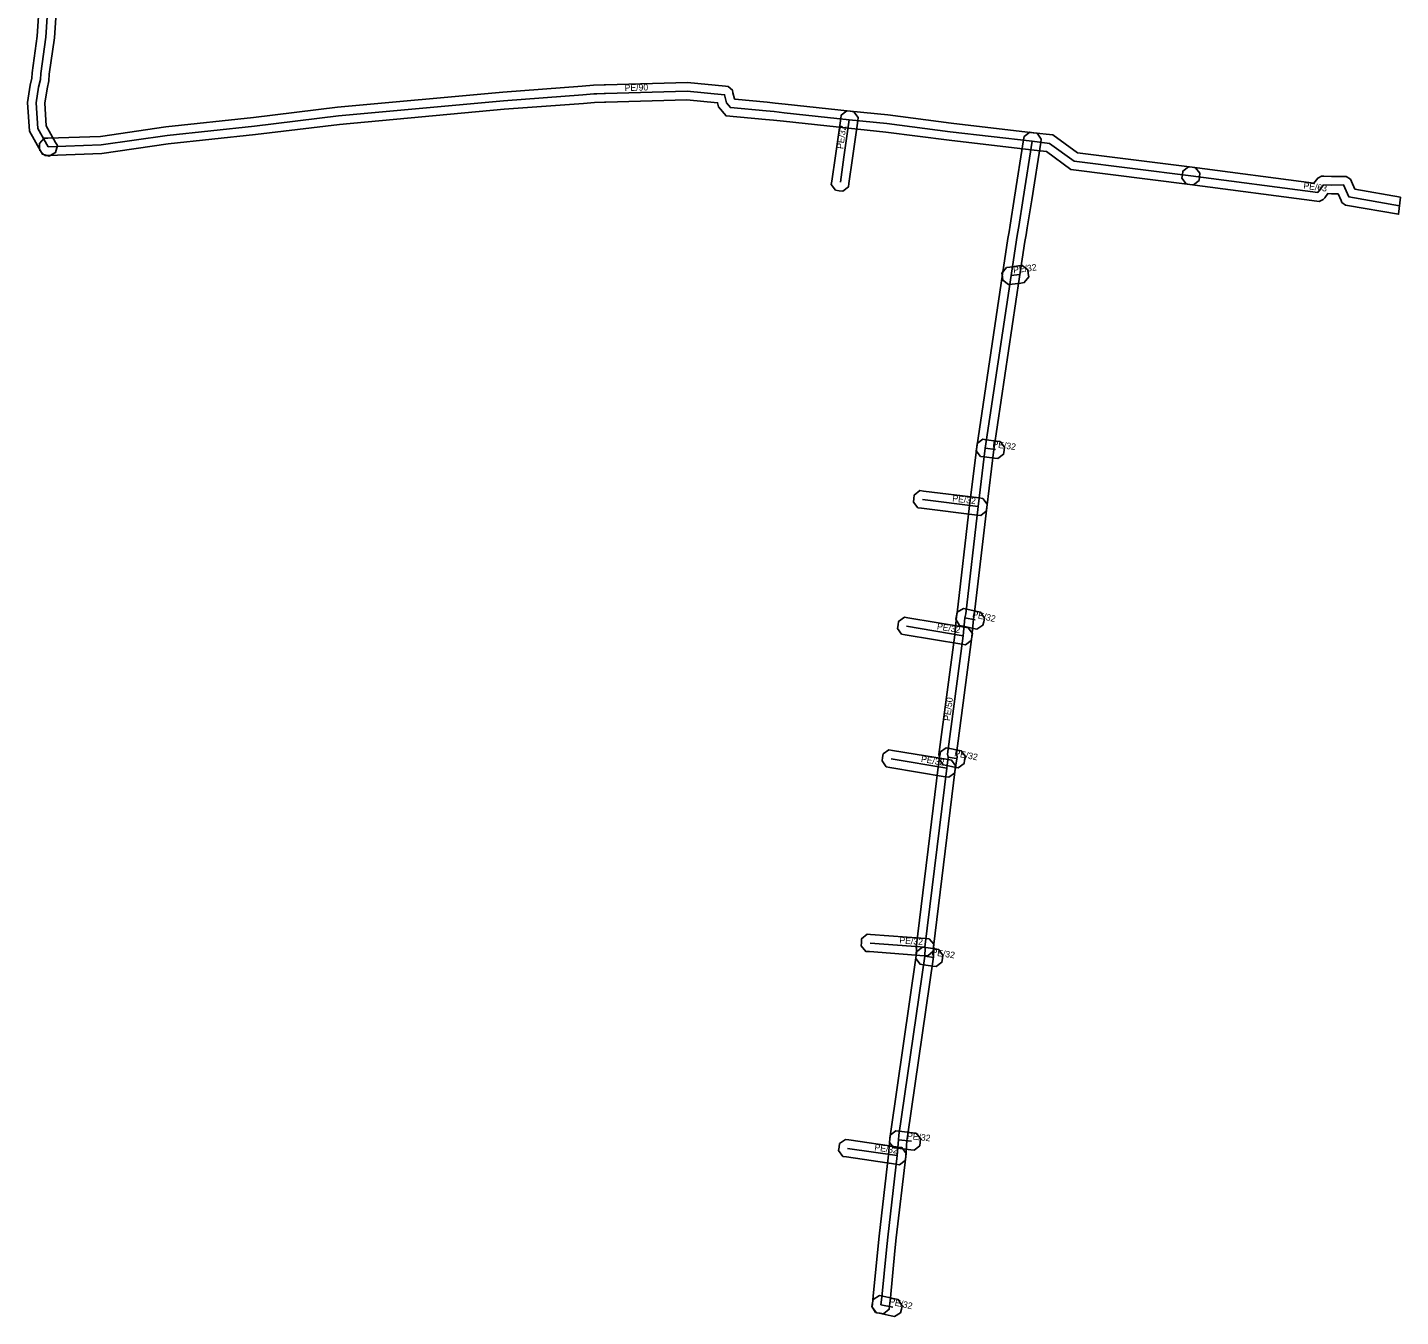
# Model space of a CAD drawing. Extents: x -772893 to -772575, y -1033735 to -1033288.
# Drawn here: x -772764.2 to -772605.1, y -1033735.2 to -1033585.9 of the extents above; entities that cross this region are included whole.
import ezdxf

# ---------------------------------------------------------------- set-up
doc = ezdxf.new("R2010")
doc.units = 0
for name, color, linetype in [('1', 7, 'Continuous'), ('24', 7, 'Continuous'), ('30', 7, 'Continuous')]:
    doc.layers.add(name, color=color, linetype=linetype)

msp = doc.modelspace()

# ---------------------------------------------------------------- linework, layer by layer
at = {"layer": '1'}
msp.add_lwpolyline([(-772760.91, -1033584.82), (-772761.08, -1033587.14), (-772761.67, -1033591.34), (-772761.7, -1033592.11), (-772761.93, -1033593.03), (-772762.18, -1033594.7), (-772762.01, -1033597.34), (-772760.93, -1033599.25), (-772760.72, -1033599.61), (-772760.95, -1033600.41), (-772761.31, -1033600.61), (-772761.67, -1033600.82), (-772762.46, -1033600.59), (-772762.67, -1033600.23), (-772763.97, -1033597.93), (-772764.19, -1033594.61), (-772763.89, -1033592.62), (-772763.69, -1033591.82), (-772763.66, -1033591.17), (-772763.07, -1033586.93), (-772762.91, -1033584.62)], dxfattribs=at)
for points in [[(-772629.13, -1033604.15), (-772629.54, -1033604.1), (-772643.31, -1033602.36), (-772646.16, -1033600.31), (-772647.92, -1033600.1), (-772657.42, -1033599), (-772664.77, -1033598.04), (-772669.1, -1033597.61), (-772676.63, -1033596.79), (-772677.79, -1033596.67), (-772678.7, -1033596.59), (-772683.27, -1033596.17), (-772684.14, -1033595.12), (-772684.25, -1033594.65), (-772687.8, -1033594.3), (-772697.19, -1033594.58), (-772697.34, -1033594.58), (-772698.52, -1033594.63), (-772699.79, -1033594.72), (-772708.97, -1033595.41), (-772728.04, -1033597.15), (-772737.78, -1033598.34), (-772747.9, -1033599.42), (-772755.58, -1033600.54), (-772761.76, -1033600.74), (-772762.18, -1033600.76), (-772762.78, -1033600.19), (-772762.8, -1033599.78), (-772762.81, -1033599.36), (-772762.24, -1033598.76), (-772761.83, -1033598.74), (-772755.75, -1033598.54), (-772748.15, -1033597.44), (-772738.01, -1033596.36), (-772728.26, -1033595.17), (-772709.14, -1033593.41), (-772699.94, -1033592.73), (-772698.64, -1033592.63), (-772697.4, -1033592.58), (-772697.25, -1033592.58), (-772687.73, -1033592.3), (-772683.34, -1033592.73), (-772683.02, -1033592.76), (-772682.54, -1033593.18), (-772682.47, -1033593.5), (-772682.3, -1033594.2), (-772682.26, -1033594.25), (-772678.52, -1033594.59), (-772677.59, -1033594.68), (-772676.41, -1033594.81), (-772668.9, -1033595.62), (-772664.54, -1033596.05), (-772657.18, -1033597.01), (-772647.69, -1033598.12), (-772645.41, -1033598.38), (-772642.56, -1033600.44), (-772629.29, -1033602.11), (-772628.88, -1033602.17), (-772628.37, -1033602.82), (-772628.43, -1033603.23), (-772628.48, -1033603.64)], [(-772667.95, -1033596.35), (-772668.01, -1033596.76), (-772668.62, -1033601.08), (-772669.04, -1033603.99), (-772669.1, -1033604.4), (-772669.76, -1033604.9), (-772670.17, -1033604.84), (-772670.58, -1033604.78), (-772671.08, -1033604.12), (-772671.02, -1033603.71), (-772670.6, -1033600.8), (-772669.99, -1033596.48), (-772669.93, -1033596.07), (-772669.27, -1033595.57), (-772668.86, -1033595.63), (-772668.45, -1033595.69)], [(-772661.25, -1033693.37), (-772661.21, -1033692.59), (-772661.24, -1033692.45), (-772658.7, -1033671.56), (-772658.55, -1033670.45), (-772658.62, -1033670.11), (-772656.78, -1033656.25), (-772656.58, -1033654.13), (-772656.5, -1033653.69), (-772655.05, -1033641.28), (-772654.23, -1033634.53), (-772651.25, -1033614.51), (-772650.63, -1033610.36), (-772650.48, -1033609.6), (-772650.35, -1033608.81), (-772649.84, -1033605.58), (-772648.8, -1033598.96), (-772648.73, -1033598.55), (-772648.06, -1033598.06), (-772647.65, -1033598.12), (-772647.24, -1033598.19), (-772646.76, -1033598.86), (-772646.82, -1033599.27), (-772647.86, -1033605.89), (-772648.37, -1033609.13), (-772648.51, -1033609.96), (-772648.65, -1033610.7), (-772649.27, -1033614.81), (-772652.25, -1033634.79), (-772653.07, -1033641.52), (-772654.52, -1033653.99), (-772654.6, -1033654.41), (-772654.8, -1033656.47), (-772656.59, -1033670.01), (-772656.51, -1033670.37), (-772656.72, -1033671.82), (-772659.22, -1033692.37), (-772659.21, -1033692.43), (-772659.25, -1033693.55), (-772662.25, -1033714.33), (-772662.32, -1033714.82), (-772662.45, -1033716.66), (-772663.55, -1033726.09), (-772663.7, -1033727.57), (-772664.22, -1033733.04), (-772664.33, -1033733.93), (-772664.37, -1033734.34), (-772665.02, -1033734.86), (-772665.43, -1033734.81), (-772665.84, -1033734.77), (-772666.36, -1033734.12), (-772666.31, -1033733.71), (-772666.21, -1033732.84), (-772665.7, -1033727.37), (-772665.53, -1033725.87), (-772664.45, -1033716.46), (-772664.31, -1033714.62), (-772664.23, -1033714.05)], [(-772605.14, -1033605.57), (-772605.36, -1033607.56), (-772611.29, -1033606.53), (-772611.53, -1033606.49), (-772611.92, -1033606.19), (-772612.03, -1033605.96), (-772612.38, -1033605.18), (-772613.14, -1033605.18), (-772613.57, -1033605.17), (-772613.91, -1033605.64), (-772614.08, -1033605.86), (-772614.58, -1033606.07), (-772614.85, -1033606.03), (-772629.55, -1033604.1), (-772629.96, -1033604.04), (-772630.46, -1033603.39), (-772630.41, -1033602.98), (-772630.35, -1033602.57), (-772629.7, -1033602.06), (-772629.29, -1033602.12), (-772615.17, -1033603.97), (-772614.86, -1033603.56), (-772614.72, -1033603.37), (-772614.28, -1033603.15), (-772614.04, -1033603.16), (-772613.12, -1033603.18), (-772611.75, -1033603.17), (-772611.45, -1033603.17), (-772610.95, -1033603.49), (-772610.83, -1033603.76), (-772610.42, -1033604.65)], [(-772650.8, -1033613.72), (-772650.39, -1033613.67), (-772649.39, -1033613.54), (-772648.98, -1033613.48), (-772648.32, -1033613.99), (-772648.27, -1033614.4), (-772648.21, -1033614.81), (-772648.72, -1033615.47), (-772649.13, -1033615.52), (-772650.13, -1033615.65), (-772650.54, -1033615.71), (-772651.2, -1033615.2), (-772651.25, -1033614.79), (-772651.31, -1033614.38)], [(-772653.53, -1033633.62), (-772653.12, -1033633.67), (-772651.94, -1033633.82), (-772651.53, -1033633.87), (-772651.02, -1033634.52), (-772651.07, -1033634.93), (-772651.12, -1033635.34), (-772651.77, -1033635.85), (-772652.18, -1033635.8), (-772653.36, -1033635.65), (-772653.78, -1033635.6), (-772654.28, -1033634.95), (-772654.23, -1033634.54), (-772654.18, -1033634.12)], [(-772653.77, -1033642.44), (-772654.18, -1033642.39), (-772660.64, -1033641.59), (-772661.05, -1033641.54), (-772661.56, -1033640.89), (-772661.51, -1033640.48), (-772661.46, -1033640.07), (-772660.81, -1033639.56), (-772660.4, -1033639.61), (-772653.94, -1033640.41), (-772653.53, -1033640.46), (-772653.02, -1033641.11), (-772653.07, -1033641.52), (-772653.12, -1033641.93)], [(-772655.55, -1033657.42), (-772655.95, -1033657.35), (-772662.52, -1033656.26), (-772662.93, -1033656.19), (-772663.42, -1033655.52), (-772663.35, -1033655.11), (-772663.28, -1033654.7), (-772662.6, -1033654.21), (-772662.2, -1033654.28), (-772655.63, -1033655.37), (-772655.22, -1033655.44), (-772654.73, -1033656.11), (-772654.8, -1033656.52), (-772654.87, -1033656.93)], [(-772655.78, -1033653.21), (-772655.38, -1033653.29), (-772654.19, -1033653.55), (-772653.78, -1033653.64), (-772653.33, -1033654.34), (-772653.42, -1033654.74), (-772653.51, -1033655.15), (-772654.21, -1033655.59), (-772654.61, -1033655.51), (-772655.8, -1033655.25), (-772656.21, -1033655.16), (-772656.66, -1033654.46), (-772656.57, -1033654.06), (-772656.48, -1033653.65)], [(-772657.46, -1033672.74), (-772657.87, -1033672.68), (-772664.31, -1033671.61), (-772664.72, -1033671.54), (-772665.2, -1033670.86), (-772665.14, -1033670.46), (-772665.07, -1033670.05), (-772664.4, -1033669.57), (-772663.99, -1033669.63), (-772657.55, -1033670.7), (-772657.14, -1033670.77), (-772656.66, -1033671.45), (-772656.72, -1033671.85), (-772656.79, -1033672.26)], [(-772657.76, -1033669.35), (-772657.35, -1033669.43), (-772656.43, -1033669.6), (-772656.02, -1033669.67), (-772655.55, -1033670.35), (-772655.63, -1033670.76), (-772655.7, -1033671.17), (-772656.38, -1033671.64), (-772656.79, -1033671.56), (-772657.71, -1033671.39), (-772658.12, -1033671.32), (-772658.59, -1033670.64), (-772658.51, -1033670.23), (-772658.44, -1033669.82)], [(-772659.89, -1033693.44), (-772660.3, -1033693.41), (-772666.66, -1033692.94), (-772667.08, -1033692.91), (-772667.62, -1033692.28), (-772667.59, -1033691.87), (-772667.56, -1033691.45), (-772666.93, -1033690.91), (-772666.52, -1033690.94), (-772660.16, -1033691.41), (-772659.74, -1033691.44), (-772659.2, -1033692.07), (-772659.23, -1033692.48), (-772659.26, -1033692.9)], [(-772660.52, -1033692.41), (-772660.11, -1033692.47), (-772659.05, -1033692.62), (-772658.64, -1033692.68), (-772658.14, -1033693.34), (-772658.2, -1033693.75), (-772658.26, -1033694.16), (-772658.92, -1033694.66), (-772659.33, -1033694.6), (-772660.39, -1033694.45), (-772660.8, -1033694.39), (-772661.3, -1033693.73), (-772661.24, -1033693.32), (-772661.18, -1033692.91)], [(-772663.19, -1033717.61), (-772663.59, -1033717.55), (-772669.33, -1033716.71), (-772669.74, -1033716.65), (-772670.24, -1033715.98), (-772670.18, -1033715.58), (-772670.12, -1033715.17), (-772669.45, -1033714.67), (-772669.05, -1033714.73), (-772663.31, -1033715.57), (-772662.9, -1033715.63), (-772662.4, -1033716.3), (-772662.46, -1033716.71), (-772662.52, -1033717.11)], [(-772663.61, -1033713.68), (-772663.2, -1033713.73), (-772661.66, -1033713.9), (-772661.25, -1033713.94), (-772660.73, -1033714.59), (-772660.78, -1033715), (-772660.82, -1033715.41), (-772661.47, -1033715.93), (-772661.88, -1033715.88), (-772663.42, -1033715.71), (-772663.83, -1033715.67), (-772664.35, -1033715.02), (-772664.3, -1033714.61), (-772664.26, -1033714.2)], [(-772665.51, -1033732.76), (-772665.11, -1033732.84), (-772663.73, -1033733.14), (-772663.32, -1033733.23), (-772662.88, -1033733.93), (-772662.96, -1033734.33), (-772663.05, -1033734.74), (-772663.75, -1033735.19), (-772664.15, -1033735.1), (-772665.53, -1033734.8), (-772665.94, -1033734.71), (-772666.39, -1033734.01), (-772666.3, -1033733.61), (-772666.21, -1033733.2)]]:
    msp.add_lwpolyline(points, close=True, dxfattribs=at)
at = {"layer": '24'}
for points in [[(-772761.91, -1033584.72), (-772762.08, -1033587.04), (-772762.66, -1033591.25), (-772762.69, -1033591.96), (-772762.91, -1033592.83), (-772763.19, -1033594.66), (-772762.99, -1033597.63), (-772761.8, -1033599.74)], [(-772629.42, -1033603.11), (-772642.94, -1033601.4), (-772645.79, -1033599.35), (-772647.81, -1033599.11), (-772657.3, -1033598.01), (-772664.66, -1033597.04), (-772669, -1033596.62), (-772676.52, -1033595.8), (-772677.69, -1033595.68), (-772678.61, -1033595.59), (-772682.76, -1033595.21), (-772683.22, -1033594.66), (-772683.44, -1033593.72), (-772687.76, -1033593.3), (-772697.22, -1033593.58), (-772697.37, -1033593.58), (-772698.24, -1033593.61), (-772698.58, -1033593.63), (-772699.87, -1033593.72), (-772709.06, -1033594.41), (-772728.15, -1033596.16), (-772737.9, -1033597.35), (-772748.02, -1033598.43), (-772755.67, -1033599.54), (-772761.8, -1033599.74)], [(-772669, -1033596.62), (-772669.61, -1033600.94), (-772670.03, -1033603.85)], [(-772647.81, -1033599.11), (-772648.85, -1033605.73), (-772649.36, -1033608.97), (-772649.49, -1033609.78), (-772649.64, -1033610.53), (-772650.26, -1033614.66), (-772653.24, -1033634.66), (-772654.06, -1033641.4), (-772655.51, -1033653.84), (-772655.59, -1033654.27), (-772655.79, -1033656.36), (-772657.61, -1033670.06), (-772657.53, -1033670.41), (-772657.71, -1033671.69), (-772660.23, -1033692.41), (-772660.21, -1033692.51), (-772660.25, -1033693.46), (-772663.24, -1033714.19), (-772663.31, -1033714.72), (-772663.45, -1033716.56), (-772664.54, -1033725.98), (-772664.7, -1033727.47), (-772665.22, -1033732.94), (-772665.32, -1033733.82)], [(-772629.42, -1033603.11), (-772614.72, -1033605.04), (-772614.06, -1033604.16), (-772613.13, -1033604.18), (-772611.74, -1033604.17), (-772611.12, -1033605.55), (-772605.25, -1033606.57)], [(-772650.26, -1033614.66), (-772649.26, -1033614.53)], [(-772653.24, -1033634.66), (-772652.06, -1033634.81)], [(-772654.06, -1033641.4), (-772660.52, -1033640.6)], [(-772655.59, -1033654.27), (-772654.4, -1033654.53)], [(-772655.79, -1033656.36), (-772662.36, -1033655.27)], [(-772657.71, -1033671.69), (-772664.15, -1033670.62)], [(-772657.53, -1033670.41), (-772656.61, -1033670.58)], [(-772660.23, -1033692.41), (-772666.59, -1033691.94)], [(-772660.25, -1033693.46), (-772659.19, -1033693.61)], [(-772663.31, -1033714.72), (-772661.77, -1033714.89)], [(-772663.45, -1033716.56), (-772669.19, -1033715.72)], [(-772665.32, -1033733.82), (-772663.94, -1033734.12)]]:
    msp.add_lwpolyline(points, dxfattribs=at)

# ---------------------------------------------------------------- texts
at = {"layer": '30'}
for s, rotation, p in [('PE/90', 1.6777, (-772695.01, -1033593.3)), ('PE/32', 81.9052, (-772669.71, -1033600.04)), ('PE/63', 352.5021, (-772616.42, -1033604.59)), ('PE/32', 7.4069, (-772649.96, -1033614.4)), ('PE/32', 352.8989, (-772652.45, -1033634.53)), ('PE/32', 352.9405, (-772657.09, -1033640.8)), ('PE/32', 347.6753, (-772654.8, -1033654.2)), ('PE/32', 350.5801, (-772658.88, -1033655.62)), ('PE/50', 82.4328, (-772657.33, -1033666.26)), ('PE/32', 349.5308, (-772656.87, -1033670.3)), ('PE/32', 350.5665, (-772660.73, -1033670.96)), ('PE/32', 355.7736, (-772663.21, -1033691.98)), ('PE/32', 351.9456, (-772659.52, -1033693.34)), ('PE/32', 353.7006, (-772662.34, -1033714.61)), ('PE/32', 351.6743, (-772666.12, -1033715.94)), ('PE/32', 347.7352, (-772664.43, -1033733.77))]:
    msp.add_text(s, height=0.75, rotation=rotation, dxfattribs=at).set_placement(p)

doc.saveas('drawing.dxf')
